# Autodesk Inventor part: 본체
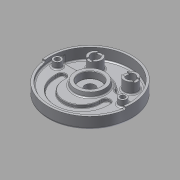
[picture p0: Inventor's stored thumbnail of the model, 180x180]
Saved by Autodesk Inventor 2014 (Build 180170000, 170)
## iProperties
Created: 2015-06
Part Number: 본체
Material: 알루미늄 6061
Document SubType Name: Modeling
Designer: MYHOME
Density: 2.71 g/cm^3
Appearance: 알루미늄 - 평지
Mass: 1381.33 g
Surface Area: 1027.7 cm^2
Volume: 509.716 cm^3
Author: MYHOME
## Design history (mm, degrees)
sketch "스케치1"
  geometry: C1 r 95 at (0, 0); 1 further point
  constraints: 1 centre point, 1 coincident
  dimensions: "d0" = 190 diameter of C1
extrude "돌출1" new body sketch "스케치1" distance "d1" = 32; taper "d2" = 0 deg
sketch "스케치2"
  geometry: C1 r 95 at (0, 0) reference
sketch "스케치3"
  geometry: C1 r 95 at (0, 0) reference; C2 r 90 at (0, 0)
  constraints: 1 centre point, 1 coincident
  dimensions: "d3" = 180 diameter of C2
extrude "돌출2" cut sketch "스케치3" distance "d4" = 25; taper "d5" = 0 deg
sketch "스케치4"
  geometry: C1 r 90 at (0, 0) reference; C2 r 15 at (-40, 52); C3 r 15 at (40, 52)
  constraints: 2 centre point
  dimensions: "d6" = 30 diameter of C2; "d7" = 30 diameter of C3; "d8" = 52 vertical distance of C1.centre C2.centre; "d9" = 52 vertical distance of C1.centre C3.centre; "d10" = 80 distance of C3.centre C2.centre; "d11" = 40 horizontal distance of C1.centre C2.centre
extrude "돌출3" join sketch "스케치4" distance "d12" = 25; taper "d13" = 0 deg
sketch "스케치5"
  geometry: C1 r 15 at (0, 0) reference; C2 r 15 at (80, 0) reference; C3 r 10 at (0, 0); C4 r 10 at (80, 0); 1 further point
  constraints: 2 centre point, 2 coincident
  dimensions: "d14" = 20 diameter of C3; "d15" = 20 diameter of C4
extrude "돌출4" cut sketch "스케치5" stored distance "d16" = 25; taper "d17" = 0 deg
sketch "스케치6"
  geometry: L1 (-6, 13.748)-(-6, -13.748); L2 (6, 13.748)-(6, -13.748); L3 (66.252, 6)-(93.748, 6); L4 (66.252, -6)-(93.748, -6); C1 r 10 at (0, 0) reference; C2 r 10 at (80, 0) reference; A1 r 15 centre (0, 0) between (-6, 13.748) and (6, 13.748) reference; A2 r 15 centre (80, 0) between (66.252, 6) and (66.252, -6) reference; 1 further point
  constraints: 8 end point, 8 point on circle, 2 parallel, 1 perpendicular, 1 vertical
  dimensions: "d18" = 12 distance between parallel lines of L2 L1; "d19" = 6 distance from line of L2 C1.centre; "d20" = 12 distance between parallel lines of L4 L3; "d21" = 6 distance from line of L3 C2.centre
extrude "돌출5" cut sketch "스케치6" distance "d22" = 3; taper "d23" = 0 deg
sketch "스케치7"
  geometry: L1 (-88.566, 16)-(-38.833, 16); L2 (38.833, 16)-(88.566, 16); C1 r 90 at (0, 0) reference; A1 r 90 centre (0, 0) between (-88.566, 16) and (88.566, 16) reference; A2 r 42 centre (0, 0) between (38.833, 16) and (-38.833, 16)
  constraints: 4 end point, 4 point on circle, 2 horizontal, 1 centre point, 1 coincident
  dimensions: "d24" = 16 vertical distance of L2.end A1.centre; "d25" = 84 diameter of A2; "d26" = 16 distance from line of A1.centre L1
extrude "돌출6" join sketch "스케치7" distance "d27" = 14; taper "d28" = 0 deg
sketch "스케치8"
  geometry: C1 r 9 at (-74, 0); C2 r 9 at (74, 0); A1 r 90 centre (0, 0) between (-88.566, 16) and (88.566, 16) reference
  constraints: 2 centre point, 2 horizontal alignment
  dimensions: "d29" = 18 diameter of C1; "d30" = 18 diameter of C2; "d31" = 148 distance of C2.centre C1.centre; "d32" = 74 distance of C2.centre A1.centre
extrude "돌출7" join sketch "스케치8" distance "d33" = 14; taper "d34" = 0 deg
sketch "스케치9"
  geometry: C1 r 35 at (0, 0); A1 r 42 centre (0, 0) between (38.833, 16) and (-38.833, 16) reference
  constraints: 1 centre point, 1 coincident
  dimensions: "d35" = 70 diameter of C1
extrude "돌출8" join sketch "스케치9" distance "d36" = 10; taper "d37" = -10 deg
sketch "스케치10"
  geometry: C1 r 33.237 at (0, 0) reference; C2 r 25 at (0, 0)
  constraints: 1 centre point, 1 coincident
  dimensions: "d38" = 50 diameter of C2
extrude "돌출9" cut sketch "스케치10" distance "d39" = 15; taper "d40" = 0 deg
sketch "스케치11"
  geometry: C1 r 25 at (0, 0) reference; C2 r 11.5 at (0, 0)
  constraints: 1 centre point, 1 coincident
  dimensions: "d41" = 23 diameter of C2
extrude "돌출10" cut sketch "스케치11" stored distance "d42" = 15; taper "d43" = 0 deg
sketch "스케치15"
  geometry: L1 (-38.833, 16)-(-88.566, 16) reference; L2 (-59, -14)-(-59, -19); L3 (-41, -14)-(-41, -19); L4 (41, -19)-(41, -14); L5 (59, -14)-(59, -19); C1 r 35 at (0, 0) reference; A1 r 9 centre (-50, -14) between (-41, -14) and (-59, -14); A2 r 9 centre (50, -14) between (59, -14) and (41, -14); A3 r 41 centre (0, -19) between (-40.992, -18.18) and (41, -19); A4 r 59 centre (0, -19) between (-58.988, -17.82) and (59, -19); 1 further point
  constraints: 10 point on circle, 8 end point, 4 centre point, 4 tangent, 3 parallel, 1 coincident, 1 perpendicular, 1 vertical alignment
  dimensions: "d64" = 9 radius of A1; "d65" = 9 radius of A2; "d66" = 14 vertical distance of C1.centre A1.centre; "d67" = 14 vertical distance of C1.centre A2.centre; "d68" = 100 distance of A2.centre A1.centre; "d69" = 50 horizontal distance of A1.centre C1.centre; "d70" = 19 distance of point (0, -19) C1.centre; "d72" = 59 radius of A4; "d73" = 41 radius of A3
extrude "돌출12" cut sketch "스케치15" distance "d74" = 7; taper "d75" = 0 deg
fillet "모깎기1" dims "d76" = 1
sketch "스케치16"
  geometry: C1 r 9 at (0, 0) reference; C2 r 9 at (148, 0) reference; C3 r 5.5 at (0, 0); C4 r 5.5 at (148, 0); 1 further point
  constraints: 2 centre point, 2 coincident
  dimensions: "d77" = 11 diameter of C3; "d78" = 11 diameter of C4
extrude "돌출13" cut sketch "스케치16" stored distance "d79" = 7; taper "d80" = 0 deg
sketch "스케치17"
  geometry: C1 r 5.5 at (74, 0) reference; C2 r 5.5 at (-74, 0) reference
hole "구멍1" sketch "스케치17" at (-74, 0), (74, 0) diameter "d81" = 18; stored, may be unused: countersink angle "d85" = 90 deg, drill point angle "d87" = 0 deg; dims "d82" = 6, "d83" = 4, "d84" = 2, "d86" = 11
fillet "모깎기2" dims "d88" = 10
node "작업 평면1"
sketch "스케치20"
  geometry: L1 (0, 0)-(-89.124, -12.526); L2 (0, 0)-(89.124, -12.526); L3 (-95, 0)-(95, 0); L4 (89.124, -12.526)-(94.075, -13.221); L5 (-89.124, -12.526)-(-94.075, -13.221); A1 r 90 centre (0, 0) between (89.124, -12.526) and (-89.124, -12.526) reference; A2 r 95 centre (0, 0) between (-94.075, -13.221) and (-95, 0) reference
  constraints: 10 end point, 6 point on circle, 2 collinear, 1 horizontal, 1 midpoint
  dimensions: "d97" = 8 deg angle of L2 L3; "d98" = 8 deg angle of L1 L3
extrude "돌출14" cut sketch "스케치20" distance "d99" = 5; taper "d100" = 0 deg
fillet "모깎기3" dims "d101" = 3
fillet "모깎기4" dims "d102" = 3
fillet "모깎기5" dims "d103" = 3
fillet "모깎기6" dims "d104" = 3
fillet "모깎기7" dims "d105" = 3
fillet "모깎기8" dims "d106" = 3
fillet "모깎기9" dims "d107" = 5
fillet "모깎기10" dims "d108" = 0.3
fillet "모깎기11" dims "d112" = 3
sketch "스케치21"
  geometry: C1 r 90 at (0, 0) reference; C2 r 68 at (0, 0)
  constraints: 1 centre point, 1 coincident, 1 other
  dimensions: "d114" = 136 diameter of C2
feature "엠보싱1" sketch "스케치21" dims "d115" = 0.5, "d116" = 0
fillet "모깎기12" dims "d117" = 3
chamfer "모따기2" distance "d119" = 1; stored, may be unused: second distance "d120" = 2, angle "d121" = 45 deg
chamfer "모따기3" distance "d122" = 1; stored, may be unused: second distance "d123" = 2, angle "d124" = 45 deg
sketch "스케치22"
  geometry: C1 r 11.5 at (0, 0) reference; C2 r 26 at (0, 0)
  constraints: 1 centre point, 1 coincident
  dimensions: "d125" = 52 diameter of C2
extrude "돌출15" join sketch "스케치22" distance "d126" = 12; taper "d127" = -15 deg
sketch "스케치23"
  geometry: C1 r 22.785 at (0, 0) reference; C2 r 11.5 at (0, 0)
  constraints: 1 centre point, 1 coincident
  dimensions: "d128" = 23 diameter of C2
extrude "돌출16" cut sketch "스케치23" stored distance "d129" = 12; taper "d130" = 0 deg
fillet "모깎기14" dims "d131" = 3
chamfer "모따기4" distance "d132" = 1; stored, may be unused: second distance "d133" = 2, angle "d134" = 45 deg
node "솔리드1"
node "투영된 루프1"
node "투영된 루프2"
other parameters: "d47" = 59, "d49" = 41, "d51" = 59, "d52" = 19, "d54" = 5, "d95" = 27
